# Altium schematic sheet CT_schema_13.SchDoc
size 390 x 278 mm
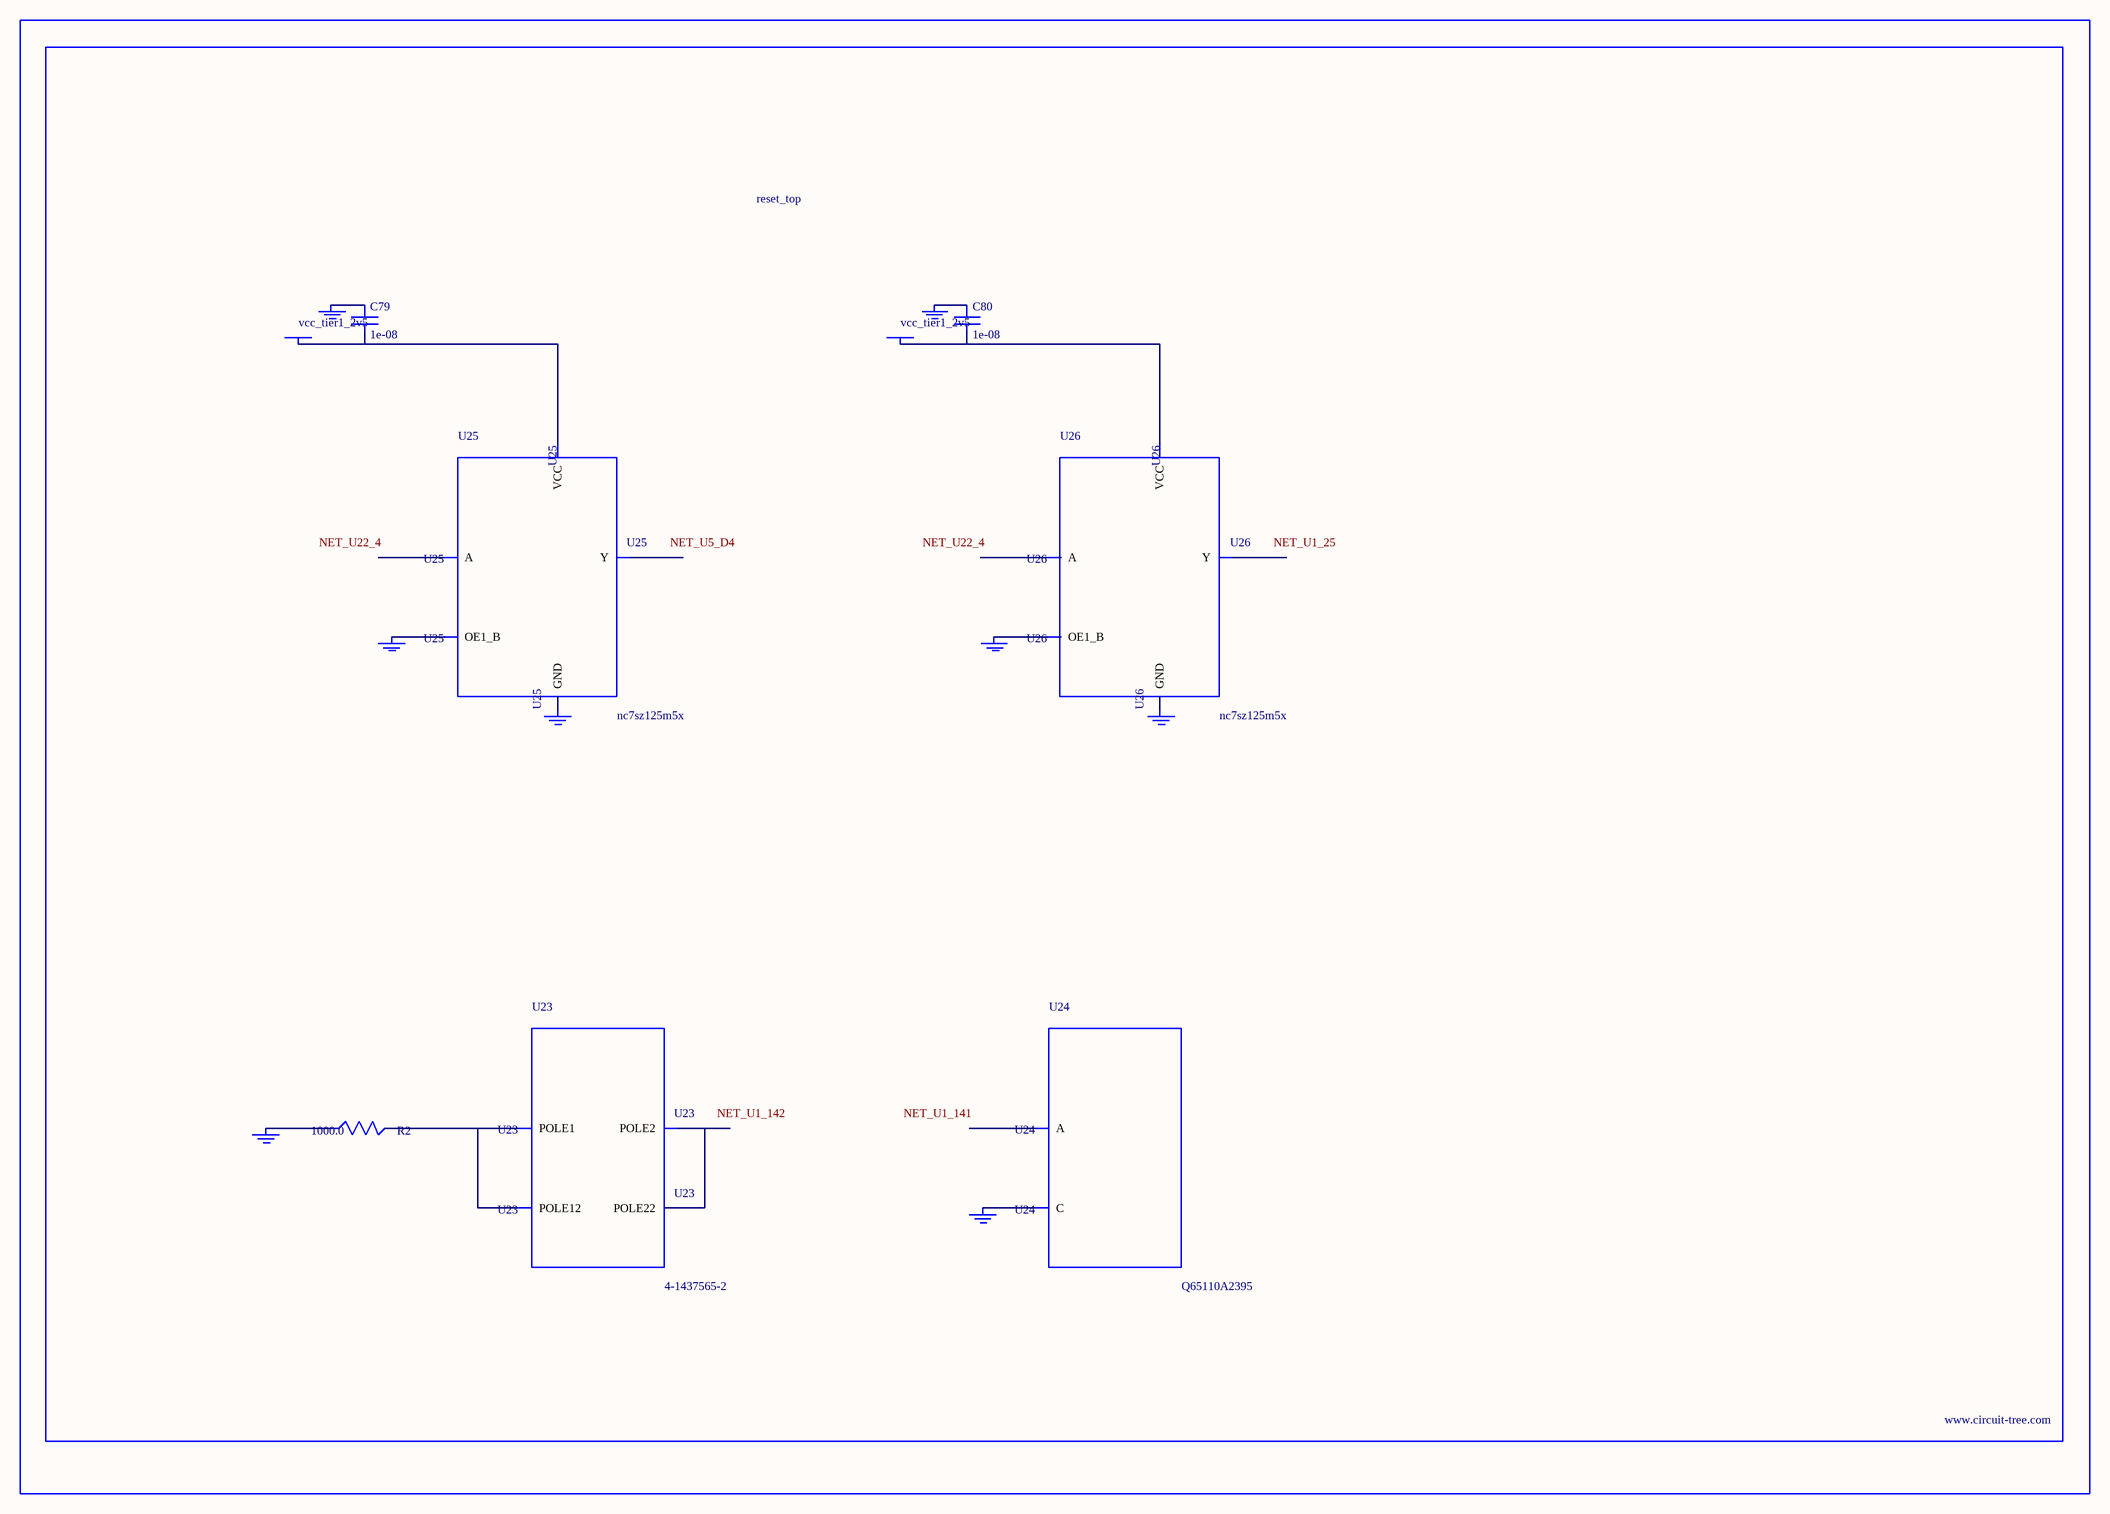
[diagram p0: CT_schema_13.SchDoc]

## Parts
BORDER12  (no value)
C79  1e-08  [C0402]
C80  1e-08  [C0402]
GND_INSTANCE_12_0  (no value)
GND_INSTANCE_12_1  (no value)
GND_INSTANCE_12_2  (no value)
GND_INSTANCE_12_3  (no value)
GND_INSTANCE_12_4  (no value)
GND_INSTANCE_12_5  (no value)
GND_INSTANCE_12_6  (no value)
GND_INSTANCE_12_7  (no value)
POWER_INSTANCE_12_0  vcc_tier1_2v5
POWER_INSTANCE_12_1  vcc_tier1_2v5
R2  1000.0  [R0603]
U23  4-1437565-2  [SW_4-1437565-2]
U24  Q65110A2395  [LGM67K-G1J2-24-Z]
U25  nc7sz125m5x  [NC7SZ125M5X]
U26  nc7sz125m5x  [NC7SZ125M5X]

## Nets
NetC79_1: C79.1 GND_INSTANCE_12_2.0(GND)
NetC79_2: C79.2 POWER_INSTANCE_12_0.0(PWR) U25.5(VCC)
NetC80_1: C80.1 GND_INSTANCE_12_5.0(GND)
NetC80_2: C80.2 POWER_INSTANCE_12_1.0(PWR) U26.5(VCC)
NetGND_INSTANCE_12_0_0: GND_INSTANCE_12_0.0(GND) R2.1
NetGND_INSTANCE_12_1_0: GND_INSTANCE_12_1.0(GND) U24.C
NetGND_INSTANCE_12_3_0: GND_INSTANCE_12_3.0(GND) U25.1(OE1_B)
NetGND_INSTANCE_12_4_0: GND_INSTANCE_12_4.0(GND) U25.3(GND)
NetGND_INSTANCE_12_6_0: GND_INSTANCE_12_6.0(GND) U26.1(OE1_B)
NetGND_INSTANCE_12_7_0: GND_INSTANCE_12_7.0(GND) U26.3(GND)
NetR2_2: R2.2 U23.1(POLE1) U23.2(POLE12)
NetU23_3: U23.3(POLE2) U23.4(POLE22)

Not connected (* = marked no-connect by the designer): U24 A; U25 2(A) 4(Y); U26 2(A) 4(Y)

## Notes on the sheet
- Labels drawn without touching a wire or pin: NET_U1_25, NET_U1_141, NET_U1_142, NET_U5_D4, NET_U22_4

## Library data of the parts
BORDER12 = BORDER_PAGE12
C79 C80 = C0402C103K3RAC
GND_INSTANCE_12_0-GND_INSTANCE_12_7 = GND
POWER_INSTANCE_12_0 POWER_INSTANCE_12_1 = PWR
R2 = RC0603JR-071KL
